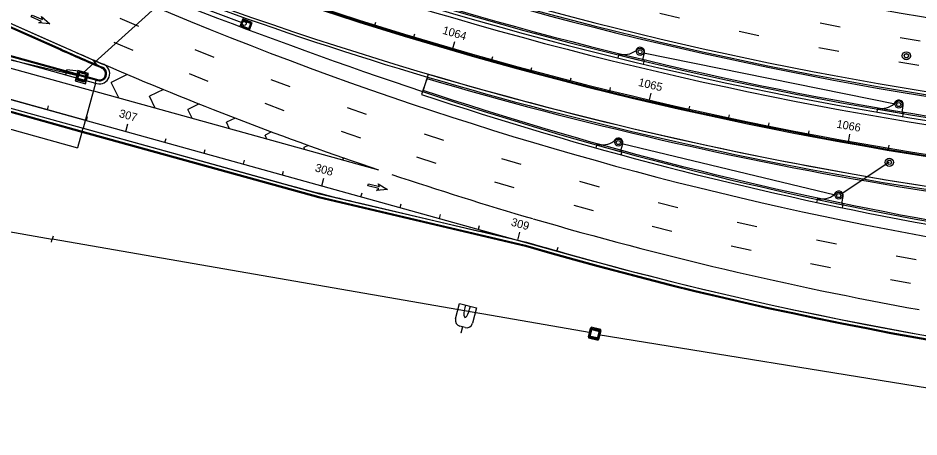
# Model space of a CAD drawing. Extents: x 468143 to 491361, y 1438528 to 1468730.
# Drawn here: x 488398.6 to 488841.6, y 1466567 to 1466773.1 of the extents above; entities that cross this region are included whole.
import ezdxf

# ---------------------------------------------------------------- set-up
doc = ezdxf.new("R2010")
doc.units = 0
doc.layers.add('Default', color=7, linetype='Continuous')
doc.layers.add('Xreference_dp', color=7, linetype='Continuous')

# ---------------------------------------------------------------- blocks, each defined once
blk = doc.blocks.new('POINT_DISPLAY')
at = {"layer": 'Default'}
blk.add_line((0, 0), (0, 0), dxfattribs=at)
blk = doc.blocks.new('InltCurb7_40')
at = {"layer": 'Default'}
for p, q in [((2.5, 4), (-2.5, 4)), ((-2.5, 4), (-2.5, 0)), ((2.5, 3.25), (-2.5, 3.25)), ((-2.5, 0.75), (2.5, 0.75)), ((-2.5, 0), (2.5, 0)), ((2.5, 0), (2.5, 4))]:
    blk.add_line(p, q, dxfattribs=at)
blk.add_lwpolyline([(-2, 0.5), (2, 0.5), (2, 3.5), (-2, 3.5)], close=True, dxfattribs=at)
blk.add_circle((-1.04, 2.19), 1, dxfattribs=at)
for p in [(-2, 3.5), (-2, 2), (-2, 2), (-2, 0.5), (0, 4), (0, 3.5), (0, 3.5), (0, 2), (0, 2), (0, 0.5), (0, 0.5), (0, 0), (0, 0), (2, 3.5), (2, 2), (2, 2), (2, 0.5)]:
    blk.add_blockref('POINT_DISPLAY', p, dxfattribs=at)
blk = doc.blocks.new('InltCurb1_35')
at = {"layer": 'Default'}
for p, q in [((2.25, 2), (2.25, 5.5)), ((-10, 2), (-10, 0)), ((-10, 1.5), (3, 1.5)), ((3, 2), (2.25, 2)), ((3, 0), (3, 2))]:
    blk.add_line(p, q, dxfattribs=at)
for radius in [1.75, 1]:
    blk.add_circle((0, 5.5), radius, dxfattribs=at)
for centre, radius, start, end in [((-9.85, 12), 10, 269.1432, 319.4677), ((0, 5.5), 2.25, 0, 180)]:
    blk.add_arc(centre, radius, start, end, dxfattribs=at)
for p in [(-1.75, 5.5), (-1.75, 5.5), (-1.62, 4.84), (-1.6, 6.2), (-1.22, 6.76), (-0.66, 7.12), (0, 7.75), (0, 7.25), (0, 7.25), (0, 5.5), (0, 5.5), (0.7, 7.1), (1.26, 6.72), (1.6, 4.8), (1.62, 6.16), (1.75, 5.5), (1.75, 5.5), (-1.26, 4.28), (-0.7, 3.9), (0, 3.75), (0, 3.75), (0, 0), (0, 0), (0.66, 3.88), (1.22, 4.24)]:
    blk.add_blockref('POINT_DISPLAY', p, dxfattribs=at)
blk = doc.blocks.new('MHCover2')
at = {"layer": 'Default'}
for radius in [2, 1.06, 1]:
    blk.add_circle((0, 0), radius, dxfattribs=at)
for p in [(-2, 0), (-2, 0), (-1.83, 0.81), (-1.39, 1.43), (-0.75, 1.85), (0, 2.5), (0, 2), (0, 2), (0, 0), (0, 0), (0, 0), (0.81, 1.83), (1.43, 1.39), (1.85, 0.75), (2, 0), (2, 0), (-1.85, -0.75), (-1.43, -1.39), (-0.81, -1.83), (0, -2), (0, -2), (0, -2.5), (0.75, -1.85), (1.39, -1.43), (1.83, -0.81)]:
    blk.add_blockref('POINT_DISPLAY', p, dxfattribs=at)
blk = doc.blocks.new('DBIDnoPvt')
at = {"layer": 'Default'}
for p, q in [((2.21, 2.71), (-2.21, 2.71)), ((-2.21, 2.71), (-2.21, -2.71)), ((-1.54, 2.23), (-1.54, -2.23)), ((1.54, 2.23), (-1.54, 2.23)), ((1.54, 2.04), (-1.54, 2.04)), ((1.54, -2.23), (1.54, 2.23)), ((2.21, -2.71), (2.21, 2.71)), ((-2.21, -2.71), (2.21, -2.71)), ((-1.54, -2.04), (1.54, -2.04)), ((-1.54, -2.23), (1.54, -2.23))]:
    blk.add_line(p, q, dxfattribs=at)
for p in [(-1.54, 2.04), (-1.54, 0), (-1.54, 0), (0, 2.71), (0, 2.04), (0, 2.04), (1.54, 2.04), (-1.54, -2.04), (0, 0), (0, 0), (0, -2.04), (0, -2.04), (0, -2.71), (1.54, 0), (1.54, 0), (1.54, -2.04)]:
    blk.add_blockref('POINT_DISPLAY', p, dxfattribs=at)
blk = doc.blocks.new('JBottom35x40')
at = {"layer": 'Default'}
for p, q in [((-2.42, 2.67), (-2.42, -2.67)), ((2.42, 2.67), (-2.42, 2.67)), ((-1.75, -2), (-1.75, 2)), ((-1.75, 2), (1.75, 2)), ((1.75, 2), (1.75, -2)), ((2.42, -2.67), (2.42, 2.67)), ((-2.42, -2.67), (2.42, -2.67)), ((1.75, -2), (-1.75, -2))]:
    blk.add_line(p, q, dxfattribs=at)
for p in [(-1.75, 2), (-1.75, 0), (-1.75, 0), (0, 2), (0, 2), (0, 2), (0, 0), (0, 0), (0, 0), (1.75, 2), (1.75, 0), (1.75, 0), (-1.75, -2), (0, -2), (0, -2), (0, -2), (1.75, -2)]:
    blk.add_blockref('POINT_DISPLAY', p, dxfattribs=at)
blk = doc.blocks.new('MESC15CMP4S')
at = {"layer": 'Default'}
for p, q in [((-0.67, 2.43), (0.67, 2.43)), ((0, 2.43), (0, 4)), ((-2.16, -3), (-2.16, 0.93)), ((2.16, 0.93), (2.16, -3)), ((2.16, -3), (-2.16, -3))]:
    blk.add_line(p, q, dxfattribs=at)
for centre, start, end in [((-0.67, 0.93), 90, 180), ((0.67, 0.93), 0, 90)]:
    blk.add_arc(centre, 1.5, start, end, dxfattribs=at)
blk.add_ellipse((0, -2.5), major_axis=(0, 2.5), ratio=0.25, start_param=4.510858, end_param=8.055336, dxfattribs=at)
for p in [(0, 4), (0, 2.43), (0, 0), (0, 0), (0, -3)]:
    blk.add_blockref('POINT_DISPLAY', p, dxfattribs=at)
blk = doc.blocks.new('JBottom40x40')
at = {"layer": 'Default'}
for p, q in [((2.67, 2.67), (-2.67, 2.67)), ((-2.67, 2.67), (-2.67, -2.67)), ((-2, -2), (-2, 2)), ((-2, 2), (2, 2)), ((2, 2), (2, -2)), ((2.67, -2.67), (2.67, 2.67)), ((-2.67, -2.67), (2.67, -2.67)), ((2, -2), (-2, -2))]:
    blk.add_line(p, q, dxfattribs=at)
for p in [(-2, 2), (-2, 0), (-2, 0), (0, 2), (0, 2), (0, 2), (0, 0), (0, 0), (0, 0), (2, 2), (-2, -2), (0, -2), (0, -2), (0, -2), (2, 0), (2, 0), (2, -2)]:
    blk.add_blockref('POINT_DISPLAY', p, dxfattribs=at)
blk = doc.blocks.new('DAMerge_2')
at = {"layer": 'Default'}
blk.add_lwpolyline([(0.71, -4.09), (0, -3.39), (3.95, 0.56), (2.42, 0.68), (7.31, 3.21), (4.77, -1.68), (4.66, -0.15), (0.71, -4.09)], dxfattribs=at)
blk = doc.blocks.new('DAMerge_6')
at = {"layer": 'Default'}
blk.add_lwpolyline([(0.71, -4.09), (0, -3.39), (3.95, 0.56), (2.42, 0.68), (7.31, 3.21), (4.77, -1.68), (4.66, -0.15), (0.71, -4.09)], dxfattribs=at)

msp = doc.modelspace()

# ---------------------------------------------------------------- linework, layer by layer
at = {"layer": 'Xreference_dp'}
for p, q in [((487909.53, 1466984.15), (488419.4, 1466757.43)), ((487909.74, 1466984.6), (488419.6, 1466757.89)), ((487910.37, 1466985.96), (488420.21, 1466759.26)), ((487949.91, 1466856.31), (488673.07, 1466655.85)), ((488431.38, 1466722.84), (487949.91, 1466856.31)), ((487948.84, 1466852.46), (488430.58, 1466718.91)), ((487948.31, 1466850.53), (488430.05, 1466716.99)), ((487948.44, 1466851.01), (488430.18, 1466717.47)), ((487946.17, 1466842.82), (488427.91, 1466709.28)), ((488436.39, 1466751.31), (488471.15, 1466782.89)), ((488508.88, 1466770.79), (488475.24, 1466783.41)), ((488375.75, 1466779.03), (488439.82, 1466750.54)), ((488448.7, 1466772.98), (488457.89, 1466769.05)), ((488723.84, 1466772.97), (488714.11, 1466775.25)), ((488573.95, 1466769.21), (488574.55, 1466771.12)), ((488802.83, 1466768.67), (488793.01, 1466770.54)), ((488360.85, 1466763.67), (488437.13, 1466742.52)), ((488360.99, 1466764.15), (488437.26, 1466743)), ((488593.07, 1466763.33), (488593.65, 1466765.25)), ((488762.9, 1466764.36), (488753.12, 1466766.43)), ((488842.22, 1466761.72), (488832.36, 1466763.38)), ((488359.29, 1466758.39), (488435.39, 1466737.3)), ((488360.45, 1466762.22), (488436.73, 1466741.08)), ((488445.77, 1466761.18), (488454.97, 1466757.26)), ((488612.25, 1466757.65), (488613.36, 1466761.49)), ((488802.14, 1466756.59), (488792.32, 1466758.46)), ((488381.3, 1466755.75), (488428.07, 1466744.77)), ((488381.3, 1466755.75), (488428.07, 1466744.77)), ((488381.3, 1466755.75), (488428.07, 1466744.77)), ((488381.3, 1466755.75), (488428.07, 1466744.77)), ((488485.6, 1466757.55), (488494.88, 1466753.82)), ((488631.48, 1466752.17), (488632.02, 1466754.1)), ((488706.19, 1466756.05), (488829.93, 1466730.84)), ((488430.46, 1466745.93), (488436.39, 1466751.31)), ((488435.37, 1466752.41), (488436.39, 1466751.31)), ((488437.4, 1466750.2), (488436.39, 1466751.31)), ((488841.54, 1466749.67), (488831.67, 1466751.32)), ((488422.62, 1466747.58), (488421.95, 1466745.17)), ((488421.95, 1466745.17), (488432.07, 1466742.37)), ((488422.36, 1466746.62), (488432.47, 1466743.81)), ((488428.43, 1466747.01), (488422.62, 1466747.58)), ((488427.78, 1466743.56), (488428.18, 1466745)), ((488432.77, 1466745.81), (488428.43, 1466747.01)), ((488432.37, 1466744.36), (488432.77, 1466745.81)), ((488452.34, 1466745.34), (488444.37, 1466741.46)), ((488482.69, 1466745.78), (488491.97, 1466742.06)), ((488599.87, 1466744.08), (488600.35, 1466745.51)), ((488650.77, 1466746.9), (488651.29, 1466748.83)), ((488436.73, 1466741.08), (488430.58, 1466718.91)), ((488436.73, 1466741.08), (488430.58, 1466718.91)), ((488431.54, 1466742.52), (488431.94, 1466743.96)), ((488432.07, 1466742.37), (488432.61, 1466744.3)), ((488432.61, 1466744.3), (488432.37, 1466744.36)), ((488436.73, 1466741.08), (488437.26, 1466743)), ((488436.73, 1466741.08), (488437.26, 1466743)), ((488436.73, 1466741.08), (488437.34, 1466740.91)), ((488437.13, 1466742.52), (488437.74, 1466742.35)), ((488437.26, 1466743), (488437.88, 1466742.83)), ((488448.11, 1466733.77), (488444.37, 1466741.46)), ((488522.84, 1466742.93), (488532.19, 1466739.41)), ((488599.87, 1466744.08), (488597.49, 1466736.97)), ((488599.63, 1466743.37), (488597.73, 1466737.68)), ((488670.12, 1466741.82), (488670.62, 1466743.76)), ((488435.66, 1466737.22), (488575.86, 1466698.36)), ((488470.05, 1466737.97), (488463.17, 1466734.62)), ((488597.49, 1466736.97), (488597.01, 1466735.55)), ((488689.52, 1466736.95), (488689.99, 1466738.89)), ((488708.96, 1466732.28), (488709.88, 1466736.18)), ((488466, 1466728.81), (488463.17, 1466734.62)), ((488413.02, 1466727.93), (488413.56, 1466729.86)), ((488487.66, 1466730.86), (488482.09, 1466728.15)), ((488484.23, 1466723.76), (488482.09, 1466728.15)), ((488519.93, 1466731.2), (488529.29, 1466727.68)), ((488560.38, 1466729.14), (488569.81, 1466725.82)), ((488728.46, 1466727.82), (488728.9, 1466729.77)), ((488432.3, 1466722.59), (488432.83, 1466724.52)), ((488505.41, 1466723.91), (488501.05, 1466721.79)), ((488748, 1466723.56), (488748.42, 1466725.51)), ((488430.05, 1466716.99), (488430.58, 1466718.91)), ((488430.05, 1466716.99), (488430.58, 1466718.91)), ((488430.58, 1466718.91), (488546.87, 1466686.68)), ((488431.2, 1466718.74), (488527.6, 1466692.02)), ((488451.57, 1466717.25), (488452.64, 1466721.1)), ((488502.57, 1466718.67), (488501.05, 1466721.79)), ((488767.58, 1466719.5), (488767.98, 1466721.46)), ((488430.05, 1466716.99), (488427.91, 1466709.28)), ((488430.05, 1466716.99), (488546.33, 1466684.75)), ((488430.18, 1466717.47), (488546.47, 1466685.23)), ((488470.84, 1466711.9), (488471.38, 1466713.83)), ((488523.3, 1466717.11), (488520.05, 1466715.53)), ((488521.01, 1466713.56), (488520.05, 1466715.53)), ((488557.49, 1466717.43), (488566.92, 1466714.12)), ((488598.22, 1466716.18), (488607.73, 1466713.07)), ((488787.21, 1466715.65), (488787.58, 1466717.62)), ((488806.88, 1466712.01), (488807.58, 1466715.95)), ((488541.34, 1466710.47), (488539.08, 1466709.37)), ((488539.54, 1466708.43), (488539.08, 1466709.37)), ((488695.46, 1466711.37), (488800.43, 1466686.09)), ((488826.58, 1466708.57), (488826.91, 1466710.54)), ((488490.12, 1466706.56), (488490.65, 1466708.49)), ((488509.39, 1466701.22), (488509.92, 1466703.15)), ((488558.91, 1466704.21), (488558.24, 1466703.88)), ((488558.6, 1466703.14), (488558.24, 1466703.88)), ((488594.49, 1466704.77), (488603.99, 1466701.66)), ((488636.34, 1466704.05), (488645.91, 1466701.15)), ((488827, 1466702.12), (488803.62, 1466686.67)), ((488528.66, 1466695.88), (488529.2, 1466697.8)), ((488547.94, 1466690.53), (488549, 1466694.39)), ((488632.86, 1466692.57), (488642.43, 1466689.67)), ((488674.71, 1466692.77), (488684.34, 1466690.08)), ((488546.41, 1466684.73), (488648.06, 1466660.88)), ((488546.53, 1466685.22), (488648.19, 1466661.37)), ((488546.87, 1466686.68), (488648.57, 1466662.82)), ((488567.21, 1466685.19), (488567.74, 1466687.12)), ((488566.33, 1466682.11), (488625.22, 1466668.3)), ((488586.48, 1466679.85), (488587.02, 1466681.77)), ((488671.84, 1466681.11), (488681.47, 1466678.42)), ((488713.33, 1466682.33), (488723.01, 1466679.85)), ((488605.76, 1466674.5), (488606.29, 1466676.43)), ((488363.32, 1466673.48), (488415.46, 1466664.37)), ((488625.03, 1466669.16), (488625.56, 1466671.09)), ((488710.45, 1466670.68), (488720.14, 1466668.2)), ((488752.16, 1466672.75), (488761.9, 1466670.49)), ((488415.81, 1466665.83), (488415.46, 1466664.37)), ((488644.3, 1466663.82), (488645.37, 1466667.67)), ((488415.12, 1466662.91), (488415.46, 1466664.37)), ((488680.41, 1466618.2), (488415.46, 1466664.37)), ((488749.29, 1466661.1), (488759.03, 1466658.83)), ((488791.2, 1466664.02), (488800.98, 1466661.97)), ((488663.58, 1466658.48), (488664.11, 1466660.4)), ((488788.32, 1466652.36), (488798.11, 1466650.32)), ((488830.41, 1466656.16), (488840.25, 1466654.33)), ((488827.54, 1466644.49), (488837.37, 1466642.65)), ((488683.82, 1466617.4), (488994.65, 1466566.98))]:
    msp.add_line(p, q, dxfattribs=at)
msp.add_lwpolyline([(488427.84, 1466743.02), (488431.22, 1466742.09), (488432.15, 1466745.46), (488428.78, 1466746.39)], close=True, dxfattribs=at)
for centre, radius, start, end in [((489145.02, 1468591.69), 1909.86, 245.36712, 306.9274), ((489145.02, 1468591.69), 1836.86, 245.36712, 266.14562), ((489145.02, 1468591.69), 1838.86, 245.36712, 266.14562), ((489145.02, 1468591.69), 1837.36, 245.36712, 266.14562), ((489145.02, 1468591.69), 1842.86, 245.36712, 265.63392), ((489145.02, 1468591.69), 1880.36, 245.36712, 266.78234), ((489145.02, 1468591.69), 1878.86, 245.36712, 266.78234), ((489145.02, 1468591.69), 1878.86, 245.36712, 266.78234), ((489145.02, 1468591.69), 1881.11, 245.36712, 266.78234), ((489145.02, 1468591.69), 1894.86, 245.36712, 267.58634), ((489145.02, 1468591.69), 1892.86, 245.36712, 267.59092), ((489145.02, 1468591.69), 1891.36, 245.36712, 267.59092), ((489145.02, 1468591.69), 1890.61, 245.36712, 263.85174), ((489145.02, 1468591.69), 1909.36, 245.36712, 267.72102), ((489145.02, 1468591.69), 1910.36, 245.37448, 267.72104), ((489412.39, 1469171.15), 2566.96, 246.02731, 251.49066), ((489095.84, 1468425.01), 1752.58, 246.02731, 253.56076), ((489145.02, 1468591.69), 1924.86, 246.95075, 267.69896), ((489167.8, 1468440.54), 1804, 246.0273, 267.4233), ((489167.8, 1468440.54), 1840, 246.0273, 246.7222), ((489167.8, 1468440.54), 1842, 246.0273, 246.7222), ((489167.8, 1468440.54), 1841.5, 246.0273, 246.7222), ((488438.68, 1466745.73), 5, 254.5061, 66.7222), ((489167.8, 1468440.54), 1840, 246.6957, 251.23385), ((488438.68, 1466745.73), 3.5, 254.5061, 66.7222), ((488438.68, 1466745.73), 3, 254.5061, 66.7222), ((489145.02, 1468591.69), 1924.86, 253.56237, 267.69896), ((489145.02, 1468591.69), 1927.11, 253.55995, 267.69896), ((489145.02, 1468591.69), 1926.36, 253.56076, 267.69896), ((489167.8, 1468440.54), 1796.5, 251.49066, 267.48938), ((489167.8, 1468440.54), 1795.75, 251.49066, 267.4904), ((489167.8, 1468440.54), 1798, 251.49066, 267.48619), ((489167.8, 1468440.54), 1840, 251.44813, 253.70804), ((488794.74, 1467655.68), 1000, 254.50611, 256.79672), ((489167.8, 1468440.54), 1840, 253.71807, 259.79058), ((488396.81, 1465694.73), 1000, 74.31594, 76.79672), ((489167.8, 1468440.54), 1854, 253.71973, 265.90975), ((489167.8, 1468440.54), 1853.5, 253.71931, 265.90975), ((489167.8, 1468440.54), 1852, 253.71807, 265.90975), ((489167.8, 1468440.54), 1852, 254.31594, 265.90975)]:
    msp.add_arc(centre, radius, start, end, dxfattribs=at)

# ---------------------------------------------------------------- block references
for name, p, rotation in [('DAMerge_2', (488408.63, 1466775.79), -68.47249683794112), ('DAMerge_6', (488408.63, 1466775.79), -68.47249683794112), ('InltCurb7_40', (488510.02, 1466768.02), -20.609107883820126), ('InltCurb1_35', (488703.18, 1466751.13), -13.752843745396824), ('MHCover2', (488835.41, 1466754.53), 86.55174435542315), ('JBottom40x40', (488429.93, 1466744), -15.49388888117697), ('POINT_DISPLAY', (488428.78, 1466746.39), -15.49388888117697), ('POINT_DISPLAY', (488430.46, 1466745.93), -15.49388888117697), ('POINT_DISPLAY', (488430.46, 1466745.93), -15.49388888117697), ('POINT_DISPLAY', (488430.6, 1466746.41), -15.49388888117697), ('POINT_DISPLAY', (488432.15, 1466745.46), -15.49388888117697), ('POINT_DISPLAY', (488427.84, 1466743.02), -15.49388888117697), ('POINT_DISPLAY', (488428.31, 1466744.71), -15.49388888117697), ('POINT_DISPLAY', (488428.31, 1466744.71), -15.49388888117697), ('POINT_DISPLAY', (488429.53, 1466742.55), -15.49388888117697), ('POINT_DISPLAY', (488429.53, 1466742.55), -15.49388888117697), ('POINT_DISPLAY', (488429.66, 1466743.04), -15.49388888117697), ('POINT_DISPLAY', (488429.66, 1466743.04), -15.49388888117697), ('POINT_DISPLAY', (488430, 1466744.24), -15.49388888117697), ('POINT_DISPLAY', (488430, 1466744.24), -15.49388888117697), ('POINT_DISPLAY', (488431.22, 1466742.09), -15.49388888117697), ('POINT_DISPLAY', (488431.68, 1466743.77), -15.49388888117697), ('POINT_DISPLAY', (488431.68, 1466743.77), -15.49388888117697), ('InltCurb1_35', (488830.69, 1466725.12), -10.152844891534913), ('InltCurb1_35', (488692.29, 1466706.54), -15.601942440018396), ('MHCover2', (488827, 1466702.12), 86.55174435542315), ('DAMerge_2', (488573.76, 1466693.24), -58.68441390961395), ('DAMerge_6', (488573.76, 1466693.24), -58.68441390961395), ('InltCurb1_35', (488801.03, 1466680.35), -11.717755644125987), ('JBottom35x40', (488682.12, 1466617.8), -13.198270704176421), ('DBIDnoPvt', (488682.12, 1466617.8), 76.80172929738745)]:
    msp.add_blockref(name, p, dxfattribs=dict(at, rotation=rotation))
msp.add_blockref('POINT_DISPLAY', (488436.39, 1466751.31), dxfattribs=at)
at = {"layer": 'Xreference_dp', "xscale": 1.9999999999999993, "yscale": 2, "rotation": 165.7420212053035}
msp.add_blockref('MESC15CMP4S', (488618.35, 1466625.85), dxfattribs=at)

# ---------------------------------------------------------------- texts
at = {"layer": 'Xreference_dp'}
for s, rotation, p in [('1064', 343.8017, (488607.02, 1466765.42)), ('1065', 346.8017, (488703.34, 1466739.76)), ('307', 344.5061, (488447.98, 1466724.47)), ('1066', 349.8017, (488800.87, 1466719.19)), ('308', 344.5061, (488544.35, 1466697.75)), ('309', 344.5061, (488640.71, 1466671.04))]:
    msp.add_text(s, height=4, rotation=rotation, dxfattribs=at).set_placement(p)

doc.saveas('drawing.dxf')
